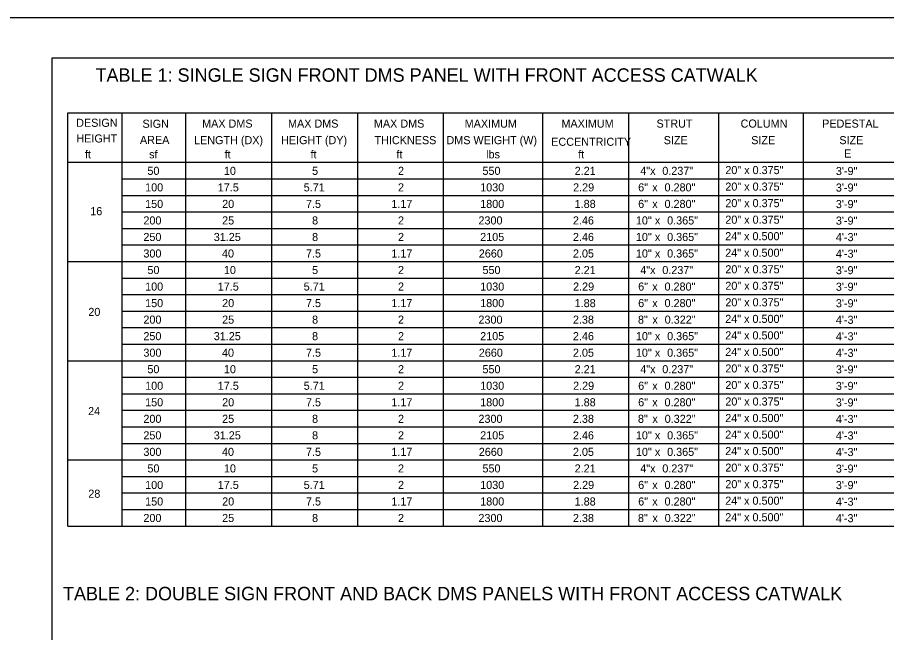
# Model space of a CAD drawing. Extents: x 3829340 to 3831660, y 499389 to 501171.
# Drawn here: x 3830208.1 to 3830530.9, y 500942.8 to 501171.2 of the extents above; entities that cross this region are included whole.
import ezdxf

# ---------------------------------------------------------------- set-up
doc = ezdxf.new("R2010")
doc.units = 0
for name, color, linetype in [('1', 7, 'Continuous'), ('2', 7, 'Continuous'), ('PLT-BNDY', 7, 'Continuous'), ('TABULATION', 7, 'Continuous')]:
    doc.layers.add(name, color=color, linetype=linetype)

msp = doc.modelspace()

# ---------------------------------------------------------------- linework, layer by layer
at = {"layer": '2'}
for p, q in [((3830220.96, 500592.19), (3830220.96, 501156.19)), ((3830220.96, 501156.19), (3831006.96, 501156.19))]:
    msp.add_line(p, q, dxfattribs=at)
at = {"layer": 'PLT-BNDY'}
msp.add_lwpolyline([(3830180.96, 501171.19), (3831021.96, 501171.19), (3831021.96, 500577.19), (3830180.96, 500577.19)], close=True, dxfattribs=at)
at = {"layer": 'TABULATION'}
for p, q in [((3830226.8, 501135.8), (3830617.55, 501135.8)), ((3830226.8, 500982.41), (3830226.8, 501135.8)), ((3830247.05, 500982.41), (3830247.05, 501135.8)), ((3830270.67, 500982.41), (3830270.67, 501135.8)), ((3830302.57, 500982.41), (3830302.57, 501135.8)), ((3830334.48, 500982.41), (3830334.48, 501135.8)), ((3830366.38, 500982.41), (3830366.38, 501135.8)), ((3830403.2, 500982.41), (3830403.2, 501135.8)), ((3830435.1, 500982.41), (3830435.1, 501135.8)), ((3830468.54, 500982.41), (3830468.54, 501135.8)), ((3830500.07, 500982.41), (3830500.07, 501135.8)), ((3830226.8, 501117.4), (3830710.51, 501117.4)), ((3830247.05, 501111.26), (3830853.16, 501111.26)), ((3830247.05, 501105.12), (3830853.16, 501105.12)), ((3830247.05, 501098.99), (3830853.16, 501098.99)), ((3830247.05, 501092.85), (3830853.16, 501092.85)), ((3830247.05, 501086.72), (3830853.16, 501086.72)), ((3830226.8, 501080.58), (3830853.16, 501080.58)), ((3830247.05, 501074.45), (3830853.16, 501074.45)), ((3830247.05, 501068.31), (3830853.16, 501068.31)), ((3830247.05, 501062.18), (3830853.16, 501062.18)), ((3830247.05, 501056.04), (3830853.16, 501056.04)), ((3830247.05, 501049.9), (3830853.16, 501049.9)), ((3830226.8, 501043.77), (3830853.16, 501043.77)), ((3830247.05, 501037.63), (3830853.16, 501037.63)), ((3830247.05, 501031.5), (3830853.16, 501031.5)), ((3830247.05, 501025.36), (3830853.16, 501025.36)), ((3830247.05, 501019.23), (3830853.16, 501019.23)), ((3830247.05, 501013.09), (3830853.16, 501013.09)), ((3830226.8, 501006.96), (3830853.16, 501006.96)), ((3830247.05, 501000.82), (3830853.16, 501000.82)), ((3830247.05, 500994.68), (3830853.16, 500994.68)), ((3830247.05, 500988.55), (3830853.16, 500988.55)), ((3830226.8, 500982.41), (3830853.16, 500982.41))]:
    msp.add_line(p, q, dxfattribs=at)

# ---------------------------------------------------------------- texts
at = {"layer": '1'}
for s, p in [('TABLE 1: SINGLE SIGN FRONT DMS PANEL WITH FRONT ACCESS CATWALK', (3830237.1, 501147.29)), ('TABLE 2: DOUBLE SIGN FRONT AND BACK DMS PANELS WITH FRONT ACCESS CATWALK', (3830225.01, 500954.83))]:
    msp.add_text(s, height=4.9999, dxfattribs=at).set_placement(p)
at = {"layer": 'TABULATION'}
for s, height, p in [('DESIGN', 3, (3830229.91, 501130.57)), ('SIGN', 3, (3830254.54, 501130.21)), ('MAX DMS', 3, (3830276.68, 501130.27)), ('MAX DMS', 3, (3830308.59, 501130.27)), ('MAX DMS', 3, (3830340.49, 501130.27)), ('MAXIMUM ', 3, (3830374.2, 501130.27)), ('MAXIMUM', 3, (3830410.13, 501130.27)), ('STRUT', 3, (3830445.43, 501130.27)), ('COLUMN', 3, (3830476.67, 501130.27)), ('PEDESTAL', 3, (3830506.96, 501130.27)), ('HEIGHT', 3, (3830230, 501124.76)), ('AREA', 3, (3830253.6, 501124.21)), ('LENGTH (DX)', 2.9996, (3830273.69, 501124.13)), ('HEIGHT (DY)', 2.9996, (3830306.02, 501124.13)), ('THICKNESS', 3, (3830340.71, 501124.13)), ('DMS WEIGHT (W)', 2.9996, (3830367.43, 501124.13)), ('SIZE', 3, (3830448.11, 501124.13)), ('SIZE', 3, (3830480.6, 501124.13)), ('SIZE', 3, (3830513.33, 501124.13)), ('ECCENTRICITY', 2.9996, (3830406.34, 501123.53)), ('ft', 3, (3830233.18, 501118.87)), ('sf', 3, (3830257, 501118.87)), ('ft', 3, (3830285.05, 501118.87)), ('ft', 3, (3830316.96, 501118.87)), ('ft', 3, (3830348.86, 501118.87)), ('lbs', 3, (3830382.17, 501118.87)), ('ft', 3, (3830416.37, 501118.87)), ('E', 3, (3830515.12, 501119.18)), ('50', 3, (3830256.37, 501112.74)), ('10', 3, (3830284.78, 501112.74)), ('5', 3, (3830317.52, 501112.74)), ('2', 3, (3830349.43, 501112.74)), ('550', 3, (3830380.8, 501112.74)), ('2.21', 3, (3830415.04, 501112.74)), ('4"x', 3, (3830439.41, 501112.74)), (' 0.237"', 3, (3830446.47, 501112.74)), ('20" x 0.375"', 2.9996, (3830471, 501113.02)), ('3\'-9"', 3, (3830512.05, 501112.67)), ('100', 3, (3830255.53, 501106.6)), ('17.5', 3, (3830282.5, 501106.6)), ('5.71', 3, (3830314.41, 501106.6)), ('2', 3, (3830349.43, 501106.6)), ('1030', 3, (3830379.96, 501106.6)), ('2.29', 3, (3830414.46, 501106.6)), ('6"', 3, (3830438.63, 501106.6)), (' x', 3, (3830442.74, 501106.6)), (' 0.280"', 3, (3830447.3, 501106.6)), ('20" x 0.375"', 2.9996, (3830471, 501106.89)), ('3\'-9"', 3, (3830512.05, 501106.54)), ('150', 3, (3830255.52, 501100.46)), ('20', 3, (3830284.13, 501100.46)), ('7.5', 3, (3830315.26, 501100.46)), ('1.17', 3, (3830346.96, 501100.46)), ('1800', 3, (3830379.96, 501100.46)), ('1.88', 3, (3830415.04, 501100.46)), ('6"', 3, (3830438.63, 501100.46)), (' x', 3, (3830442.74, 501100.46)), (' 0.280"', 3, (3830447.3, 501100.46)), ('20" x 0.375"', 2.9996, (3830471, 501100.75)), ('3\'-9"', 3, (3830512.05, 501100.4)), ('16', 3, (3830235.14, 501097.77)), ('20" x 0.375"', 2.9996, (3830471, 501094.61)), ('200', 3, (3830254.88, 501094.33)), ('25', 3, (3830284.12, 501094.33)), ('8', 3, (3830317.52, 501094.33)), ('2', 3, (3830349.43, 501094.33)), ('2300', 3, (3830379.31, 501094.33)), ('2.46', 3, (3830414.39, 501094.33)), ('10"', 3, (3830437.78, 501094.33)), (' x', 3, (3830443.71, 501094.33)), (' 0.365"', 3, (3830448.27, 501094.33)), ('3\'-9"', 3, (3830512.05, 501094.27)), ('250', 3, (3830254.87, 501088.19)), ('31.25', 3, (3830281.01, 501088.19)), ('8', 3, (3830317.52, 501088.19)), ('2', 3, (3830349.43, 501088.19)), ('2105', 3, (3830379.95, 501088.19)), ('2.46', 3, (3830414.39, 501088.19)), ('10"', 3, (3830437.78, 501088.19)), (' 0.365"', 3, (3830448.27, 501088.19)), ('24" x 0.500"', 2.9996, (3830470.96, 501088.48)), (' x', 3, (3830443.71, 501088.19)), ('4\'-3"', 3, (3830512.05, 501088.13)), ('300', 3, (3830254.88, 501082.06)), ('40', 3, (3830284.06, 501082.06)), ('7.5', 3, (3830315.26, 501082.06)), ('1.17', 3, (3830346.96, 501082.06)), ('2660', 3, (3830379.44, 501082.06)), ('2.05', 3, (3830414.4, 501082.06)), ('10"', 3, (3830437.78, 501082.06)), (' 0.365"', 3, (3830448.27, 501082.06)), ('24" x 0.500"', 2.9996, (3830470.96, 501082.34)), ('4\'-3"', 3, (3830512.05, 501081.99)), (' x', 3, (3830443.71, 501082.06)), ('50', 3, (3830256.37, 501075.92)), ('10', 3, (3830284.78, 501075.92)), ('5', 3, (3830317.52, 501075.92)), ('2', 3, (3830349.43, 501075.92)), ('550', 3, (3830380.8, 501075.92)), ('2.21', 3, (3830415.04, 501075.92)), ('4"x', 3, (3830439.41, 501075.92)), (' 0.237"', 3, (3830446.47, 501075.92)), ('20" x 0.375"', 2.9996, (3830471, 501076.21)), ('3\'-9"', 3, (3830512.05, 501075.86)), ('100', 3, (3830255.53, 501069.79)), ('17.5', 3, (3830282.5, 501069.79)), ('5.71', 3, (3830314.41, 501069.79)), ('2', 3, (3830349.43, 501069.79)), ('1030', 3, (3830379.96, 501069.79)), ('2.29', 3, (3830414.46, 501069.79)), ('6"', 3, (3830438.63, 501069.79)), (' x', 3, (3830442.74, 501069.79)), (' 0.280"', 3, (3830447.3, 501069.79)), ('20" x 0.375"', 2.9996, (3830471, 501070.07)), ('3\'-9"', 3, (3830512.05, 501069.72)), ('150', 3, (3830255.52, 501063.65)), ('20', 3, (3830284.13, 501063.65)), ('7.5', 3, (3830315.26, 501063.65)), ('1.17', 3, (3830346.96, 501063.65)), ('1800', 3, (3830379.96, 501063.65)), ('1.88', 3, (3830415.04, 501063.65)), ('6"', 3, (3830438.63, 501063.65)), (' x', 3, (3830442.74, 501063.65)), (' 0.280"', 3, (3830447.3, 501063.65)), ('20" x 0.375"', 2.9996, (3830471, 501063.94)), ('3\'-9"', 3, (3830512.05, 501063.59)), ('20', 3, (3830234.43, 501060.38)), ('200', 3, (3830254.88, 501057.51)), ('25', 3, (3830284.12, 501057.51)), ('8', 3, (3830317.52, 501057.51)), ('2', 3, (3830349.43, 501057.51)), ('2300', 3, (3830379.31, 501057.51)), ('2.38', 3, (3830414.39, 501057.51)), ('8"', 3, (3830438.55, 501057.51)), (' x', 3, (3830442.8, 501057.51)), (' 0.322"', 3, (3830447.36, 501057.51)), ('24" x 0.500"', 2.9996, (3830470.96, 501057.8)), ('4\'-3"', 3, (3830512.05, 501057.45)), ('250', 3, (3830254.87, 501051.38)), ('31.25', 3, (3830281.01, 501051.38)), ('8', 3, (3830317.52, 501051.38)), ('2', 3, (3830349.43, 501051.38)), ('2105', 3, (3830379.95, 501051.38)), ('2.46', 3, (3830414.39, 501051.38)), ('10"', 3, (3830437.78, 501051.38)), (' x', 3, (3830443.71, 501051.38)), (' 0.365"', 3, (3830448.27, 501051.38)), ('24" x 0.500"', 2.9996, (3830470.96, 501051.67)), ('4\'-3"', 3, (3830512.05, 501051.32)), ('300', 3, (3830254.88, 501045.24)), ('40', 3, (3830284.06, 501045.24)), ('7.5', 3, (3830315.26, 501045.24)), ('1.17', 3, (3830346.96, 501045.24)), ('2660', 3, (3830379.44, 501045.24)), ('2.05', 3, (3830414.4, 501045.24)), ('10"', 3, (3830437.78, 501045.24)), (' x', 3, (3830443.71, 501045.24)), (' 0.365"', 3, (3830448.27, 501045.24)), ('24" x 0.500"', 2.9996, (3830470.96, 501045.53)), ('4\'-3"', 3, (3830512.05, 501045.18)), ('50', 3, (3830256.37, 501039.11)), ('10', 3, (3830284.78, 501039.11)), ('5', 3, (3830317.52, 501039.11)), ('2', 3, (3830349.43, 501039.11)), ('550', 3, (3830380.8, 501039.11)), ('2.21', 3, (3830415.04, 501039.11)), ('4"x', 3, (3830439.41, 501039.11)), (' 0.237"', 3, (3830446.47, 501039.11)), ('20" x 0.375"', 2.9996, (3830471, 501039.39)), ('3\'-9"', 3, (3830512.05, 501039.05)), ('100', 3, (3830255.53, 501032.97)), ('17.5', 3, (3830282.5, 501032.97)), ('5.71', 3, (3830314.41, 501032.97)), ('2', 3, (3830349.43, 501032.97)), ('1030', 3, (3830379.96, 501032.97)), ('2.29', 3, (3830414.46, 501032.97)), ('6"', 3, (3830438.63, 501032.97)), (' x', 3, (3830442.74, 501032.97)), (' 0.280"', 3, (3830447.3, 501032.97)), ('20" x 0.375"', 2.9996, (3830471, 501033.26)), ('3\'-9"', 3, (3830512.05, 501032.91)), ('150', 3, (3830255.52, 501026.84)), ('20', 3, (3830284.13, 501026.84)), ('1800', 3, (3830379.96, 501026.84)), ('1.88', 3, (3830415.04, 501026.84)), ('6"', 3, (3830438.63, 501026.84)), (' 0.280"', 3, (3830447.3, 501026.84)), ('20" x 0.375"', 2.9996, (3830471, 501027.12)), ('7.5', 3, (3830315.26, 501026.84)), ('1.17', 3, (3830346.96, 501026.84)), (' x', 3, (3830442.74, 501026.84)), ('3\'-9"', 3, (3830512.05, 501026.77)), ('24', 3, (3830234.35, 501023.57)), ('200', 3, (3830254.88, 501020.7)), ('25', 3, (3830284.12, 501020.7)), ('8', 3, (3830317.52, 501020.7)), ('2', 3, (3830349.43, 501020.7)), ('2300', 3, (3830379.31, 501020.7)), ('2.38', 3, (3830414.39, 501020.7)), ('8"', 3, (3830438.55, 501020.7)), (' 0.322"', 3, (3830447.36, 501020.7)), ('24" x 0.500"', 2.9996, (3830470.96, 501020.99)), ('4\'-3"', 3, (3830512.05, 501020.64)), (' x', 3, (3830442.8, 501020.7)), ('250', 3, (3830254.87, 501014.57)), ('31.25', 3, (3830281.01, 501014.57)), ('8', 3, (3830317.52, 501014.57)), ('2', 3, (3830349.43, 501014.57)), ('2105', 3, (3830379.95, 501014.57)), ('2.46', 3, (3830414.39, 501014.57)), ('10"', 3, (3830437.78, 501014.57)), (' 0.365"', 3, (3830448.27, 501014.57)), ('24" x 0.500"', 2.9996, (3830470.96, 501014.85)), ('4\'-3"', 3, (3830512.05, 501014.5)), (' x', 3, (3830443.71, 501014.57)), ('300', 3, (3830254.88, 501008.43)), ('40', 3, (3830284.06, 501008.43)), ('7.5', 3, (3830315.26, 501008.43)), ('1.17', 3, (3830346.96, 501008.43)), ('2660', 3, (3830379.44, 501008.43)), ('2.05', 3, (3830414.4, 501008.43)), ('10"', 3, (3830437.78, 501008.43)), (' x', 3, (3830443.71, 501008.43)), (' 0.365"', 3, (3830448.27, 501008.43)), ('24" x 0.500"', 2.9996, (3830470.96, 501008.72)), ('4\'-3"', 3, (3830512.05, 501008.37)), ('50', 3, (3830256.37, 501002.29)), ('10', 3, (3830284.78, 501002.29)), ('5', 3, (3830317.52, 501002.29)), ('2', 3, (3830349.43, 501002.29)), ('550', 3, (3830380.8, 501002.29)), ('2.21', 3, (3830415.04, 501002.29)), ('4"x', 3, (3830439.41, 501002.29)), (' 0.237"', 3, (3830446.47, 501002.29)), ('20" x 0.375"', 2.9996, (3830471, 501002.58)), ('3\'-9"', 3, (3830512.05, 501002.23)), ('100', 3, (3830255.53, 500996.16)), ('17.5', 3, (3830282.5, 500996.16)), ('5.71', 3, (3830314.41, 500996.16)), ('2', 3, (3830349.43, 500996.16)), ('1030', 3, (3830379.96, 500996.16)), ('2.29', 3, (3830414.46, 500996.16)), ('6"', 3, (3830438.63, 500996.16)), (' x', 3, (3830442.74, 500996.16)), (' 0.280"', 3, (3830447.3, 500996.16)), ('20" x 0.375"', 2.9996, (3830471, 500996.45)), ('3\'-9"', 3, (3830512.05, 500996.1)), ('28', 3, (3830234.42, 500992.9)), ('150', 3, (3830255.52, 500990.02)), ('20', 3, (3830284.13, 500990.02)), ('7.5', 3, (3830315.26, 500990.02)), ('1.17', 3, (3830346.96, 500990.02)), ('1800', 3, (3830379.96, 500990.02)), ('1.88', 3, (3830415.04, 500990.02)), ('6"', 3, (3830438.63, 500990.02)), (' x', 3, (3830442.74, 500990.02)), (' 0.280"', 3, (3830447.3, 500990.02)), ('24" x 0.500"', 2.9996, (3830470.96, 500990.31)), ('4\'-3"', 3, (3830512.05, 500989.96)), ('200', 3, (3830254.88, 500983.89)), ('25', 3, (3830284.12, 500983.89)), ('8', 3, (3830317.52, 500983.89)), ('2', 3, (3830349.43, 500983.89)), ('2300', 3, (3830379.31, 500983.89)), ('2.38', 3, (3830414.39, 500983.89)), ('8"', 3, (3830438.55, 500983.89)), (' x', 3, (3830442.8, 500983.89)), (' 0.322"', 3, (3830447.36, 500983.89)), ('24" x 0.500"', 2.9996, (3830470.96, 500984.17)), ('4\'-3"', 3, (3830512.05, 500983.82))]:
    msp.add_text(s, height=height, dxfattribs=at).set_placement(p)

doc.saveas('drawing.dxf')
